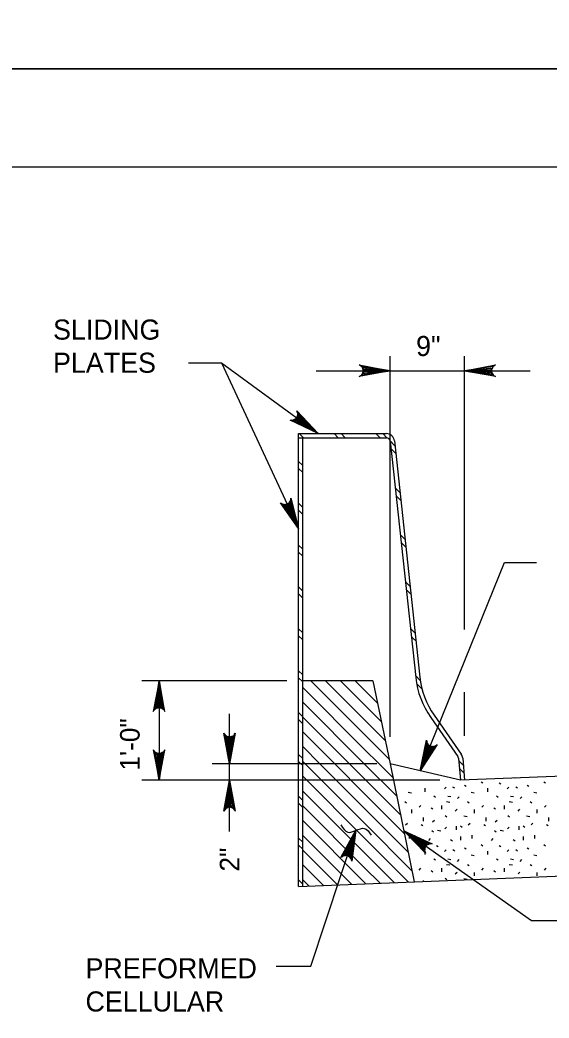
# Model space of a CAD drawing. Extents: x 638167 to 640248, y 296544 to 298920.
# Drawn here: x 639671.1 to 639752.2, y 296993.3 to 297146 of the extents above; entities that cross this region are included whole.
import ezdxf

# ---------------------------------------------------------------- set-up
doc = ezdxf.new("R2010")
doc.units = 0
doc.layers.add('1', color=7, linetype='Continuous')
doc.layers.add('PLT-BNDY', color=7, linetype='Continuous')

msp = doc.modelspace()

# ---------------------------------------------------------------- linework, layer by layer
at = {"layer": '1'}
for p, q in [((639832.78, 297123.48), (639046.78, 297123.48)), ((639727.8, 297036.32), (639727.8, 297094.56)), ((639739.23, 297052.72), (639739.23, 297094.56)), ((639696.92, 297093.54), (639702.01, 297093.54)), ((639702.01, 297093.54), (639716.8, 297082.71)), ((639702.01, 297093.54), (639713.81, 297068.21)), ((639716.48, 297092.32), (639749.28, 297092.32)), ((639713.81, 297082.71), (639727.21, 297082.71)), ((639713.81, 297013.42), (639713.81, 297082.71)), ((639713.81, 297082.08), (639727.24, 297082.08)), ((639714.53, 297082.08), (639713.9, 297082.71)), ((639714.45, 297013.45), (639714.45, 297082.08)), ((639719.87, 297082.08), (639719.23, 297082.71)), ((639720.93, 297082.08), (639720.3, 297082.71)), ((639726.27, 297082.08), (639725.63, 297082.71)), ((639727.33, 297082.08), (639726.7, 297082.71)), ((639728.55, 297080.86), (639727.83, 297081.58)), ((639727.84, 297081.54), (639731.74, 297045.4)), ((639728.68, 297079.66), (639727.96, 297080.38)), ((639728.47, 297081.58), (639732.37, 297045.46)), ((639714.45, 297077.82), (639713.81, 297078.45)), ((639714.45, 297076.75), (639713.81, 297077.38)), ((639729.32, 297073.69), (639728.61, 297074.4)), ((639729.45, 297072.49), (639728.74, 297073.21)), ((639714.45, 297071.42), (639713.81, 297072.05)), ((639714.45, 297070.35), (639713.81, 297070.98)), ((639730.1, 297066.51), (639729.38, 297067.23)), ((639714.45, 297065.02), (639713.81, 297065.65)), ((639730.23, 297065.31), (639729.51, 297066.03)), ((639714.45, 297063.95), (639713.81, 297064.58)), ((639732.44, 297031.11), (639745.32, 297062.98)), ((639745.32, 297062.98), (639750.21, 297062.98)), ((639714.45, 297058.62), (639713.81, 297059.25)), ((639730.87, 297059.34), (639730.16, 297060.05)), ((639731, 297058.14), (639730.29, 297058.86)), ((639714.45, 297057.55), (639713.81, 297058.18)), ((639714.45, 297052.22), (639713.81, 297052.85)), ((639731.19, 297052.62), (639730.93, 297052.88)), ((639731.19, 297052.62), (639731.65, 297052.16)), ((639714.45, 297051.15), (639713.81, 297051.78)), ((639731.19, 297051.53), (639731.07, 297051.65)), ((639731.78, 297050.94), (639731.19, 297051.53)), ((639714.45, 297045.79), (639713.81, 297046.43)), ((639714.45, 297044.73), (639713.81, 297045.36)), ((639732.44, 297044.95), (639731.71, 297045.68)), ((639711.99, 297044.91), (639689.79, 297044.91)), ((639692.44, 297044.91), (639692.44, 297029.67)), ((639725.19, 297044.91), (639714.45, 297044.91)), ((639723.86, 297034.46), (639714.45, 297043.87)), ((639723.86, 297036.72), (639715.68, 297044.91)), ((639723.86, 297038.99), (639717.94, 297044.91)), ((639723.86, 297041.25), (639720.2, 297044.91)), ((639723.86, 297043.51), (639722.47, 297044.91)), ((639725.89, 297041.48), (639723.86, 297043.51)), ((639725.19, 297044.91), (639727.8, 297032.21)), ((639732.72, 297043.6), (639731.88, 297044.44)), ((639739.23, 297036.49), (639739.23, 297043.16)), ((639723.86, 297032.2), (639714.45, 297041.61)), ((639726.48, 297038.63), (639723.86, 297041.25)), ((639703.23, 297021.83), (639703.23, 297039.85)), ((639714.45, 297039.39), (639713.81, 297040.03)), ((639714.45, 297038.33), (639713.81, 297038.96)), ((639721.6, 297032.2), (639714.45, 297039.35)), ((639727.07, 297035.78), (639723.86, 297038.99)), ((639734.03, 297039.28), (639738.17, 297033.33)), ((639734.55, 297039.64), (639738.7, 297033.68)), ((639719.34, 297032.2), (639714.45, 297037.08)), ((639727.65, 297032.93), (639723.86, 297036.72)), ((639717.07, 297032.2), (639714.45, 297034.82)), ((639726.12, 297032.2), (639723.86, 297034.46)), ((639714.45, 297032.99), (639713.81, 297033.63)), ((639738.28, 297033.04), (639738.58, 297029.67)), ((639738.93, 297033.07), (639739.23, 297029.69)), ((639725.78, 297032.21), (639700.59, 297032.21)), ((639714.45, 297031.93), (639713.81, 297032.56)), ((639714.81, 297032.2), (639714.45, 297032.56)), ((639723.86, 297023.15), (639714.81, 297032.2)), ((639723.86, 297025.41), (639717.07, 297032.2)), ((639723.86, 297027.67), (639719.34, 297032.2)), ((639723.86, 297029.93), (639721.6, 297032.2)), ((639728.82, 297027.24), (639723.86, 297032.2)), ((639728.24, 297030.09), (639726.12, 297032.2)), ((639738.58, 297029.67), (639727.8, 297032.21)), ((639727.8, 297032.21), (639731.51, 297014.13)), ((639739.03, 297031.96), (639738.31, 297032.68)), ((639739.13, 297030.79), (639738.41, 297031.51)), ((639787.91, 297031.64), (639738.58, 297029.67)), ((639723.86, 297020.88), (639714.45, 297030.3)), ((639729.41, 297024.39), (639723.86, 297029.93)), ((639746.95, 297029.98), (639746.93, 297030)), ((639735.43, 297029.67), (639689.79, 297029.67)), ((639733.19, 297027.91), (639733.19, 297028.45)), ((639736.13, 297028.36), (639736.4, 297028.63)), ((639737.71, 297028.45), (639737.44, 297028.63)), ((639739.47, 297028.72), (639739.2, 297028.9)), ((639742.02, 297029.22), (639741.75, 297029.4)), ((639742.79, 297027.91), (639742.79, 297028.45)), ((639744.78, 297029.08), (639744.51, 297029.26)), ((639745.73, 297028.36), (639746, 297028.63)), ((639747.31, 297028.45), (639747.04, 297028.63)), ((639749.07, 297028.72), (639748.8, 297028.9)), ((639751.62, 297029.22), (639751.35, 297029.4)), ((639714.45, 297026.59), (639713.81, 297027.23)), ((639723.86, 297018.62), (639714.45, 297028.03)), ((639729.99, 297021.54), (639723.86, 297027.67)), ((639730.6, 297027.86), (639731.1, 297027.77)), ((639734.77, 297027.05), (639734.5, 297027.23)), ((639736.63, 297027.27), (639737.12, 297027.18)), ((639738.12, 297026.87), (639738.39, 297027.14)), ((639740.2, 297027.86), (639740.7, 297027.77)), ((639744.37, 297027.05), (639744.1, 297027.23)), ((639746.23, 297027.27), (639746.72, 297027.18)), ((639747.72, 297026.87), (639747.99, 297027.14)), ((639749.8, 297027.86), (639750.3, 297027.77)), ((639714.45, 297025.53), (639713.81, 297026.16)), ((639723.86, 297016.36), (639714.45, 297025.77)), ((639730.58, 297018.69), (639723.86, 297025.41)), ((639730.33, 297026.19), (639730.06, 297026.37)), ((639731.14, 297024.65), (639731.14, 297025.19)), ((639732.24, 297025.55), (639732.51, 297025.83)), ((639734.37, 297025.24), (639734.09, 297025.42)), ((639735.72, 297025.28), (639735.72, 297025.83)), ((639736.45, 297026.41), (639736.94, 297026.32)), ((639737.8, 297024.97), (639738.07, 297025.24)), ((639739.93, 297026.19), (639739.66, 297026.37)), ((639740.74, 297024.65), (639740.74, 297025.19)), ((639741.84, 297025.55), (639742.11, 297025.83)), ((639743.97, 297025.24), (639743.69, 297025.42)), ((639745.32, 297025.28), (639745.32, 297025.83)), ((639746.05, 297026.41), (639746.54, 297026.32)), ((639747.4, 297024.97), (639747.67, 297025.24)), ((639749.53, 297026.19), (639749.26, 297026.37)), ((639750.34, 297024.65), (639750.34, 297025.19)), ((639751.44, 297025.55), (639751.71, 297025.83)), ((639732.92, 297023.41), (639732.92, 297023.96)), ((639734.32, 297023.32), (639734.59, 297023.59)), ((639736.49, 297024.05), (639736.22, 297024.23)), ((639739.11, 297024.23), (639739.61, 297024.14)), ((639742.52, 297023.41), (639742.52, 297023.96)), ((639743.92, 297023.32), (639744.19, 297023.59)), ((639746.09, 297024.05), (639745.82, 297024.23)), ((639748.71, 297024.23), (639749.21, 297024.14)), ((639752.12, 297023.41), (639752.12, 297023.96)), ((639723.86, 297014.1), (639714.45, 297023.51)), ((639731.16, 297015.85), (639723.86, 297023.15)), ((639730.19, 297022.87), (639730.46, 297023.14)), ((639732.83, 297022.69), (639732.56, 297022.87)), ((639735.09, 297022.06), (639735.59, 297021.97)), ((639736.17, 297022.24), (639736.45, 297022.51)), ((639737.98, 297022.1), (639737.98, 297022.65)), ((639738.84, 297022.46), (639738.57, 297022.65)), ((639739.79, 297022.87), (639740.06, 297023.14)), ((639742.43, 297022.69), (639742.16, 297022.87)), ((639744.69, 297022.06), (639745.19, 297021.97)), ((639745.77, 297022.24), (639746.05, 297022.51)), ((639747.58, 297022.1), (639747.58, 297022.65)), ((639748.44, 297022.46), (639748.17, 297022.65)), ((639749.39, 297022.87), (639749.66, 297023.14)), ((639752.03, 297022.69), (639751.76, 297022.87)), ((639714.45, 297020.19), (639713.81, 297020.83)), ((639721.95, 297013.75), (639714.45, 297021.24)), ((639715.66, 297001.24), (639722.59, 297022.03)), ((639730.65, 297014.1), (639723.86, 297020.88)), ((639749.48, 297008.17), (639729.91, 297021.94)), ((639730.78, 297020.75), (639730.78, 297021.29)), ((639733.73, 297020.48), (639734, 297020.75)), ((639734.46, 297021.74), (639734.19, 297021.92)), ((639737.35, 297020.38), (639737.08, 297020.57)), ((639738.62, 297020.52), (639738.62, 297021.06)), ((639740.38, 297020.75), (639740.38, 297021.29)), ((639743.33, 297020.48), (639743.6, 297020.75)), ((639744.06, 297021.74), (639743.79, 297021.92)), ((639746.95, 297020.38), (639746.68, 297020.57)), ((639748.22, 297020.52), (639748.22, 297021.06)), ((639749.98, 297020.75), (639749.98, 297021.29)), ((639714.45, 297019.13), (639713.81, 297019.76)), ((639732.42, 297019.62), (639732.15, 297019.8)), ((639735.18, 297019.48), (639734.91, 297019.66)), ((639736.13, 297018.76), (639736.4, 297019.03)), ((639737.71, 297018.85), (639737.44, 297019.03)), ((639739.47, 297019.12), (639739.2, 297019.3)), ((639742.02, 297019.62), (639741.75, 297019.8)), ((639744.78, 297019.48), (639744.51, 297019.66)), ((639745.73, 297018.76), (639746, 297019.03)), ((639747.31, 297018.85), (639747.04, 297019.03)), ((639749.07, 297019.12), (639748.8, 297019.3)), ((639751.62, 297019.62), (639751.35, 297019.8)), ((639719.77, 297013.66), (639714.45, 297018.98)), ((639728.47, 297014.01), (639723.86, 297018.62)), ((639733.19, 297018.31), (639733.19, 297018.85)), ((639734.77, 297017.45), (639734.5, 297017.63)), ((639736.63, 297017.67), (639737.12, 297017.58)), ((639738.12, 297017.27), (639738.39, 297017.54)), ((639740.2, 297018.26), (639740.7, 297018.17)), ((639742.79, 297018.31), (639742.79, 297018.85)), ((639744.37, 297017.45), (639744.1, 297017.63)), ((639746.23, 297017.67), (639746.72, 297017.58)), ((639747.72, 297017.27), (639747.99, 297017.54)), ((639749.8, 297018.26), (639750.3, 297018.17)), ((639713.81, 297013.42), (639788.51, 297016.41)), ((639717.59, 297013.57), (639714.45, 297016.72)), ((639726.3, 297013.92), (639723.86, 297016.36)), ((639732.24, 297015.95), (639732.51, 297016.23)), ((639735.72, 297015.68), (639735.72, 297016.23)), ((639736.45, 297016.81), (639736.94, 297016.72)), ((639739.93, 297016.59), (639739.66, 297016.77)), ((639741.84, 297015.95), (639742.11, 297016.23)), ((639745.32, 297015.68), (639745.32, 297016.23)), ((639746.05, 297016.81), (639746.54, 297016.72)), ((639749.53, 297016.59), (639749.26, 297016.77)), ((639751.44, 297015.95), (639751.71, 297016.23)), ((639714.45, 297013.79), (639713.81, 297014.43)), ((639715.42, 297013.49), (639714.45, 297014.46)), ((639734.37, 297015.64), (639734.09, 297015.82)), ((639736.49, 297014.45), (639736.22, 297014.63)), ((639737.8, 297015.37), (639738.07, 297015.64)), ((639739.11, 297014.63), (639739.61, 297014.54)), ((639740.74, 297015.05), (639740.74, 297015.59)), ((639743.97, 297015.64), (639743.69, 297015.82)), ((639747.4, 297015.37), (639747.67, 297015.64)), ((639750.34, 297015.05), (639750.34, 297015.59)), ((639724.12, 297013.83), (639723.86, 297014.1)), ((639732.92, 297014.19), (639732.92, 297014.36)), ((639753.76, 297008.17), (639749.48, 297008.17)), ((639710.37, 297001.24), (639715.66, 297001.24))]:
    msp.add_line(p, q, dxfattribs=at)
for points in [[(639727.8, 297092.32), (639723.1, 297091.44), (639723.28, 297091.56), (639723.46, 297091.69), (639723.56, 297091.85), (639723.65, 297092), (639723.68, 297092.16), (639723.71, 297092.32), (639723.68, 297092.48), (639723.65, 297092.63), (639723.56, 297092.79), (639723.46, 297092.95), (639723.28, 297093.07), (639723.1, 297093.2), (639727.8, 297092.32), (639723.28, 297093.07), (639723.46, 297092.95), (639727.8, 297092.32), (639723.56, 297092.79), (639723.65, 297092.63), (639727.8, 297092.32), (639723.68, 297092.48), (639723.71, 297092.32), (639727.8, 297092.32), (639723.68, 297092.16), (639723.65, 297092), (639727.8, 297092.32), (639723.56, 297091.85), (639723.46, 297091.69), (639727.8, 297092.32), (639723.28, 297091.56)], [(639739.23, 297092.32), (639743.93, 297093.2), (639743.75, 297093.07), (639743.57, 297092.95), (639743.47, 297092.79), (639743.38, 297092.63), (639743.35, 297092.48), (639743.33, 297092.32), (639743.35, 297092.16), (639743.38, 297092), (639743.47, 297091.85), (639743.57, 297091.69), (639743.75, 297091.56), (639743.93, 297091.44), (639739.23, 297092.32), (639743.75, 297091.56), (639743.57, 297091.69), (639739.23, 297092.32), (639743.47, 297091.85), (639743.38, 297092), (639739.23, 297092.32), (639743.35, 297092.16), (639743.33, 297092.32), (639739.23, 297092.32), (639743.35, 297092.48), (639743.38, 297092.63), (639739.23, 297092.32), (639743.47, 297092.79), (639743.57, 297092.95), (639739.23, 297092.32), (639743.75, 297093.07)], [(639716.8, 297082.71), (639712.49, 297084.78), (639712.71, 297084.77), (639712.93, 297084.77), (639713.1, 297084.84), (639713.27, 297084.91), (639713.38, 297085.02), (639713.5, 297085.13), (639713.57, 297085.27), (639713.64, 297085.42), (639713.66, 297085.6), (639713.68, 297085.78), (639713.6, 297085.99), (639713.53, 297086.2), (639716.8, 297082.71), (639713.6, 297085.99), (639713.68, 297085.78), (639716.8, 297082.71), (639713.66, 297085.6), (639713.64, 297085.42), (639716.8, 297082.71), (639713.57, 297085.27), (639713.5, 297085.13), (639716.8, 297082.71), (639713.38, 297085.02), (639713.27, 297084.91), (639716.8, 297082.71), (639713.1, 297084.84), (639712.93, 297084.77), (639716.8, 297082.71), (639712.71, 297084.77)], [(639713.81, 297068.21), (639711.03, 297072.1), (639711.22, 297071.99), (639711.41, 297071.88), (639711.59, 297071.86), (639711.78, 297071.84), (639711.93, 297071.88), (639712.09, 297071.92), (639712.22, 297072.02), (639712.35, 297072.11), (639712.45, 297072.26), (639712.55, 297072.41), (639712.59, 297072.63), (639712.63, 297072.84), (639713.81, 297068.21), (639712.59, 297072.63), (639712.55, 297072.41), (639713.81, 297068.21), (639712.45, 297072.26), (639712.35, 297072.11), (639713.81, 297068.21), (639712.22, 297072.02), (639712.09, 297071.92), (639713.81, 297068.21), (639711.93, 297071.88), (639711.78, 297071.84), (639713.81, 297068.21), (639711.59, 297071.86), (639711.41, 297071.88), (639713.81, 297068.21), (639711.22, 297071.99)], [(639692.44, 297044.91), (639691.55, 297040.21), (639691.68, 297040.39), (639691.81, 297040.57), (639691.96, 297040.66), (639692.12, 297040.76), (639692.28, 297040.78), (639692.44, 297040.81), (639692.59, 297040.78), (639692.75, 297040.76), (639692.91, 297040.66), (639693.07, 297040.57), (639693.19, 297040.39), (639693.32, 297040.21), (639692.44, 297044.91), (639693.19, 297040.39), (639693.07, 297040.57), (639692.44, 297044.91), (639692.91, 297040.66), (639692.75, 297040.76), (639692.44, 297044.91), (639692.59, 297040.78), (639692.44, 297040.81), (639692.44, 297044.91), (639692.28, 297040.78), (639692.12, 297040.76), (639692.44, 297044.91), (639691.96, 297040.66), (639691.81, 297040.57), (639692.44, 297044.91), (639691.68, 297040.39)], [(639703.23, 297032.21), (639702.35, 297036.9), (639702.48, 297036.72), (639702.6, 297036.54), (639702.76, 297036.45), (639702.92, 297036.35), (639703.08, 297036.33), (639703.23, 297036.3), (639703.39, 297036.33), (639703.55, 297036.35), (639703.71, 297036.45), (639703.86, 297036.54), (639703.99, 297036.72), (639704.11, 297036.9), (639703.23, 297032.21), (639703.99, 297036.72), (639703.86, 297036.54), (639703.23, 297032.21), (639703.71, 297036.45), (639703.55, 297036.35), (639703.23, 297032.21), (639703.39, 297036.33), (639703.23, 297036.3), (639703.23, 297032.21), (639703.08, 297036.33), (639702.92, 297036.35), (639703.23, 297032.21), (639702.76, 297036.45), (639702.6, 297036.54), (639703.23, 297032.21), (639702.48, 297036.72)], [(639732.44, 297031.11), (639733.4, 297035.79), (639733.45, 297035.58), (639733.5, 297035.36), (639733.61, 297035.22), (639733.72, 297035.07), (639733.85, 297034.99), (639733.99, 297034.9), (639734.14, 297034.87), (639734.3, 297034.83), (639734.48, 297034.86), (639734.66, 297034.89), (639734.85, 297035.01), (639735.03, 297035.13), (639732.44, 297031.11), (639734.85, 297035.01), (639734.66, 297034.89), (639732.44, 297031.11), (639734.48, 297034.86), (639734.3, 297034.83), (639732.44, 297031.11), (639734.14, 297034.87), (639733.99, 297034.9), (639732.44, 297031.11), (639733.85, 297034.99), (639733.72, 297035.07), (639732.44, 297031.11), (639733.61, 297035.22), (639733.5, 297035.36), (639732.44, 297031.11), (639733.45, 297035.58)], [(639692.44, 297029.67), (639693.32, 297034.36), (639693.19, 297034.18), (639693.07, 297034), (639692.91, 297033.91), (639692.75, 297033.81), (639692.59, 297033.79), (639692.44, 297033.76), (639692.28, 297033.79), (639692.12, 297033.81), (639691.96, 297033.91), (639691.81, 297034), (639691.68, 297034.18), (639691.55, 297034.36), (639692.44, 297029.67), (639691.68, 297034.18), (639691.81, 297034), (639692.44, 297029.67), (639691.96, 297033.91), (639692.12, 297033.81), (639692.44, 297029.67), (639692.28, 297033.79), (639692.44, 297033.76), (639692.44, 297029.67), (639692.59, 297033.79), (639692.75, 297033.81), (639692.44, 297029.67), (639692.91, 297033.91), (639693.07, 297034), (639692.44, 297029.67), (639693.19, 297034.18)], [(639703.23, 297029.67), (639704.11, 297024.97), (639703.99, 297025.15), (639703.86, 297025.33), (639703.71, 297025.42), (639703.55, 297025.52), (639703.39, 297025.54), (639703.23, 297025.57), (639703.08, 297025.54), (639702.92, 297025.52), (639702.76, 297025.42), (639702.6, 297025.33), (639702.48, 297025.15), (639702.35, 297024.97), (639703.23, 297029.67), (639702.48, 297025.15), (639702.6, 297025.33), (639703.23, 297029.67), (639702.76, 297025.42), (639702.92, 297025.52), (639703.23, 297029.67), (639703.08, 297025.54), (639703.23, 297025.57), (639703.23, 297029.67), (639703.39, 297025.54), (639703.55, 297025.52), (639703.23, 297029.67), (639703.71, 297025.42), (639703.86, 297025.33), (639703.23, 297029.67), (639703.99, 297025.15)], [(639722.59, 297022.03), (639721.94, 297017.29), (639721.88, 297017.5), (639721.82, 297017.71), (639721.7, 297017.85), (639721.58, 297017.99), (639721.44, 297018.07), (639721.29, 297018.14), (639721.14, 297018.17), (639720.98, 297018.19), (639720.8, 297018.15), (639720.62, 297018.11), (639720.44, 297017.98), (639720.27, 297017.85), (639722.59, 297022.03), (639720.44, 297017.98), (639720.62, 297018.11), (639722.59, 297022.03), (639720.8, 297018.15), (639720.98, 297018.19), (639722.59, 297022.03), (639721.14, 297018.17), (639721.29, 297018.14), (639722.59, 297022.03), (639721.44, 297018.07), (639721.58, 297017.99), (639722.59, 297022.03), (639721.7, 297017.85), (639721.82, 297017.71), (639722.59, 297022.03), (639721.88, 297017.5)], [(639729.91, 297021.94), (639734.26, 297019.96), (639734.04, 297019.96), (639733.82, 297019.96), (639733.65, 297019.88), (639733.48, 297019.81), (639733.37, 297019.7), (639733.26, 297019.58), (639733.19, 297019.44), (639733.12, 297019.29), (639733.11, 297019.11), (639733.09, 297018.93), (639733.17, 297018.72), (639733.25, 297018.52), (639729.91, 297021.94), (639733.17, 297018.72), (639733.09, 297018.93), (639729.91, 297021.94), (639733.11, 297019.11), (639733.12, 297019.29), (639729.91, 297021.94), (639733.19, 297019.44), (639733.26, 297019.58), (639729.91, 297021.94), (639733.37, 297019.7), (639733.48, 297019.81), (639729.91, 297021.94), (639733.65, 297019.88), (639733.82, 297019.96), (639729.91, 297021.94), (639734.04, 297019.96)]]:
    msp.add_lwpolyline(points, dxfattribs=at)
for centre, radius, start, end in [((639727.21, 297081.44), 1.27, 6.1633, 90), ((639727.24, 297081.47), 0.604, 6.1633, 90), ((639744.84, 297046.81), 13.18, 186.1633, 214.8545), ((639744.84, 297046.81), 12.54, 186.1633, 214.8545), ((639737.68, 297032.99), 0.604, 5.1262, 34.8545), ((639737.66, 297032.95), 1.27, 5.1262, 34.8545)]:
    msp.add_arc(centre, radius, start, end, dxfattribs=at)
msp.add_spline([(639720.28, 297022.85), (639721.34, 297021.73), (639723.86, 297022.32), (639724.92, 297021.28)], degree=3, dxfattribs=at)
at = {"layer": 'PLT-BNDY'}
for points in [[(639007.78, 297732.48), (639848.78, 297732.48), (639848.78, 297138.48), (639007.78, 297138.48)], [(639007.78, 297138.48), (639848.78, 297138.48), (639848.78, 296544.48), (639007.78, 296544.48)]]:
    msp.add_lwpolyline(points, close=True, dxfattribs=at)

# ---------------------------------------------------------------- texts
at = {"layer": '1'}
for s, p in [('SLIDING', (639676.2, 297097.08)), ('9"', (639731.79, 297094.57)), ('PLATES', (639676.2, 297092.01)), ('PREFORMED', (639681.17, 296999.38)), ('CELLULAR', (639681.17, 296994.31))]:
    msp.add_text(s, height=3.072, dxfattribs=at).set_placement(p)
for s, p in [('1\'-0"', (639689.46, 297031.17)), ('2"', (639704.73, 297015.72))]:
    msp.add_text(s, height=3, rotation=90, dxfattribs=at).set_placement(p)

doc.saveas('drawing.dxf')
